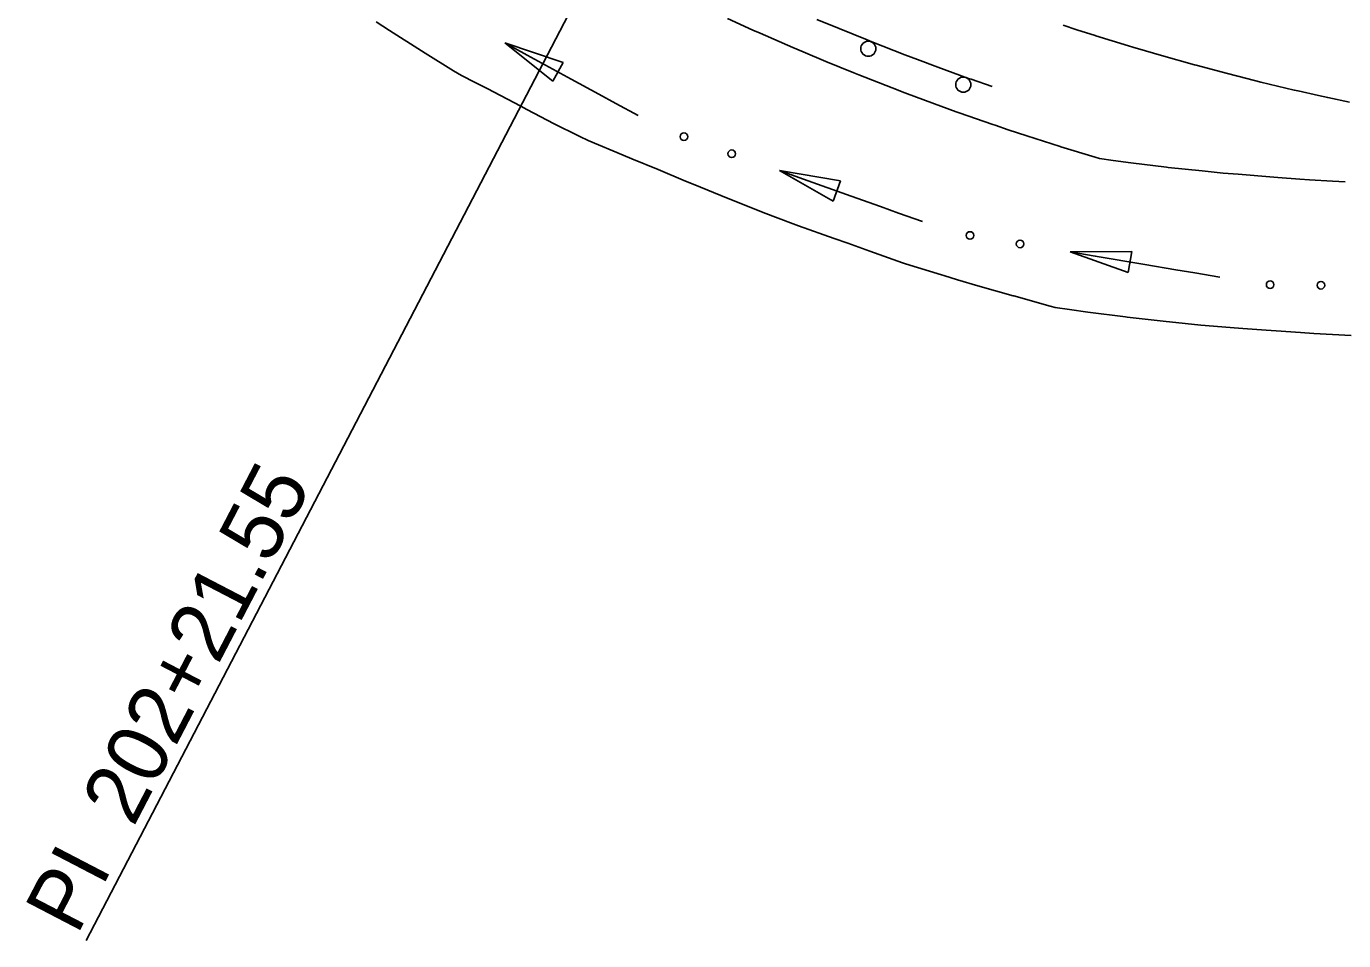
# Model space of a CAD drawing. Extents: x 1556849 to 1559393, y 1802592 to 1804749.
# Drawn here: x 1558400.6 to 1558530.6, y 1804329.1 to 1804419.4 of the extents above; entities that cross this region are included whole.
import ezdxf

# ---------------------------------------------------------------- set-up
doc = ezdxf.new("R2010")
doc.units = 0
for name, color, linetype in [('R_Horz Alg Annot', 7, 'Continuous'), ('R_Proposed Const Limits_Cut', 7, 'Continuous'), ('R_Proposed Road_Lane', 7, 'Continuous'), ('R_Proposed Road_Shoulder', 7, 'Continuous'), ('R_Steel', 7, 'Continuous'), ('R_Water', 7, 'Continuous')]:
    doc.layers.add(name, color=color, linetype=linetype)

msp = doc.modelspace()

# ---------------------------------------------------------------- linework, layer by layer
at = {"layer": 'R_Horz Alg Annot'}
msp.add_lwpolyline([(1558461.87, 1804435.55), (1558406.46, 1804329.11)], dxfattribs=at)
at = {"layer": 'R_Proposed Const Limits_Cut'}
msp.add_lwpolyline([(1558435.11, 1804419.88), (1558436.42, 1804419.02), (1558439.57, 1804417), (1558439.93, 1804416.77), (1558442.75, 1804415.02), (1558443.53, 1804414.56), (1558444.89, 1804413.88), (1558446.07, 1804413.29), (1558449.37, 1804411.54), (1558449.97, 1804411.22), (1558452.69, 1804409.81), (1558455.07, 1804408.61), (1558455.22, 1804408.54), (1558456.04, 1804408.16), (1558459.49, 1804406.69), (1558460.35, 1804406.35), (1558462.96, 1804405.29), (1558465.64, 1804404.15), (1558466.4, 1804403.84), (1558469.86, 1804402.43), (1558470.94, 1804401.99), (1558473.33, 1804401.05), (1558476.28, 1804399.92), (1558476.81, 1804399.72), (1558480.33, 1804398.46), (1558481.67, 1804398.01), (1558483.84, 1804397.22), (1558487.06, 1804396.08), (1558487.36, 1804395.98), (1558490.92, 1804394.87), (1558491.15, 1804394.8), (1558492.52, 1804394.39), (1558494.5, 1804393.81), (1558498.01, 1804392.82), (1558498.08, 1804392.8), (1558501.67, 1804391.8), (1558502.14, 1804391.66), (1558503.57, 1804391.46), (1558505.37, 1804391.21), (1558509.1, 1804390.73), (1558509.27, 1804390.71), (1558512.82, 1804390.3), (1558514.98, 1804390.07), (1558516.53, 1804389.91), (1558520.26, 1804389.62), (1558520.69, 1804389.59), (1558522.97, 1804389.42), (1558523.98, 1804389.35), (1558526.38, 1804389.18), (1558527.69, 1804389.1), (1558531.39, 1804388.9)], dxfattribs=at)
at = {"layer": 'R_Proposed Road_Lane'}
msp.add_lwpolyline([(1558502.94, 1804419.54), (1558504.28, 1804419.1), (1558506.1, 1804418.52), (1558506.17, 1804418.5), (1558509.4, 1804417.5), (1558509.83, 1804417.38), (1558511.07, 1804417.01), (1558512.65, 1804416.55), (1558515.91, 1804415.64), (1558516.07, 1804415.59), (1558519.18, 1804414.76), (1558521.09, 1804414.27), (1558522.46, 1804413.93), (1558525.76, 1804413.14), (1558526.13, 1804413.05), (1558528.16, 1804412.59), (1558529.06, 1804412.39), (1558531.2, 1804411.93)], dxfattribs=at)
at = {"layer": 'R_Proposed Road_Shoulder'}
msp.add_lwpolyline([(1558469.79, 1804420.2), (1558472.3, 1804419.06), (1558473.01, 1804418.75), (1558476.24, 1804417.34), (1558477.26, 1804416.9), (1558479.5, 1804415.97), (1558482.27, 1804414.84), (1558482.77, 1804414.64), (1558486.05, 1804413.35), (1558487.31, 1804412.87), (1558489.36, 1804412.1), (1558492.39, 1804411), (1558492.67, 1804410.9), (1558496.01, 1804409.73), (1558496.22, 1804409.66), (1558497.5, 1804409.22), (1558499.35, 1804408.61), (1558502.65, 1804407.55), (1558502.72, 1804407.53), (1558506.09, 1804406.49), (1558506.53, 1804406.36), (1558507.89, 1804406.17), (1558509.61, 1804405.95), (1558513.14, 1804405.52), (1558513.31, 1804405.5), (1558516.68, 1804405.14), (1558518.73, 1804404.94), (1558520.21, 1804404.81), (1558523.74, 1804404.52), (1558524.14, 1804404.49), (1558526.31, 1804404.34), (1558527.27, 1804404.27), (1558529.55, 1804404.14), (1558530.79, 1804404.08)], dxfattribs=at)
at = {"layer": 'R_Steel'}
msp.add_lwpolyline([(1558478.63, 1804420.12), (1558480.83, 1804419.2), (1558483.58, 1804418.08), (1558484.06, 1804417.89), (1558487.32, 1804416.61), (1558488.55, 1804416.14), (1558490.57, 1804415.38), (1558493.58, 1804414.29), (1558493.84, 1804414.2), (1558495.93, 1804413.47)], dxfattribs=at)
for centre in [(1558483.7, 1804417.22), (1558493.08, 1804413.67)]:
    msp.add_circle(centre, 0.75, dxfattribs=at)
at = {"layer": 'R_Water'}
for p, q in [((1558447.79, 1804417.8), (1558452.55, 1804414)), ((1558453.56, 1804415.86), (1558447.79, 1804417.8)), ((1558452.55, 1804414), (1558453.56, 1804415.86)), ((1558474.93, 1804405.19), (1558480.22, 1804402.17)), ((1558480.94, 1804404.16), (1558474.93, 1804405.19)), ((1558480.22, 1804402.17), (1558480.94, 1804404.16)), ((1558509.71, 1804397.19), (1558503.62, 1804397.14)), ((1558503.62, 1804397.14), (1558509.36, 1804395.11)), ((1558509.36, 1804395.11), (1558509.71, 1804397.19))]:
    msp.add_line(p, q, dxfattribs=at)
for points in [[(1558460.96, 1804410.62), (1558458.75, 1804411.82), (1558457.09, 1804412.73), (1558454.37, 1804414.21), (1558450, 1804416.59), (1558447.79, 1804417.8)], [(1558489.06, 1804400.14), (1558486.68, 1804400.99), (1558484.91, 1804401.62), (1558481.99, 1804402.66), (1558477.3, 1804404.34), (1558474.93, 1804405.19)], [(1558518.41, 1804394.66), (1558515.93, 1804395.08), (1558514.07, 1804395.39), (1558511.01, 1804395.9), (1558506.1, 1804396.73), (1558503.62, 1804397.14)]]:
    msp.add_lwpolyline(points, dxfattribs=at)
for centre in [(1558465.49, 1804408.53), (1558470.21, 1804406.84), (1558493.74, 1804398.77), (1558498.68, 1804397.94), (1558523.38, 1804393.91), (1558528.39, 1804393.85)]:
    msp.add_circle(centre, 0.375, dxfattribs=at)

# ---------------------------------------------------------------- texts
at = {"layer": 'R_Horz Alg Annot'}
msp.add_text('PI  202+21.55', height=6, rotation=62.5, dxfattribs=at).set_placement((1558405.57, 1804329.57))

doc.saveas('drawing.dxf')
